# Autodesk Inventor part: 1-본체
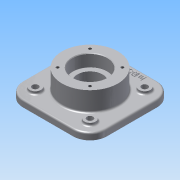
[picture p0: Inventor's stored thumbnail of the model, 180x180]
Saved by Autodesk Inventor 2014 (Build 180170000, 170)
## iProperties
Created: 2015-09
Part Number: 1-본체
Material: 알루미늄 6061
Document SubType Name: Modeling
Designer: study
Density: 2.71 g/cm^3
Appearance: 알루미늄 - 평지
Mass: 1464.68 g
Surface Area: 800.934 cm^2
Volume: 540.471 cm^3
Author: study
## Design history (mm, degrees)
sketch "스케치1"
  geometry: L1 (75, -75)-(-75, -75); L2 (-75, -75)-(-75, 75); L3 (-75, 75)-(75, 75); L4 (75, 75)-(75, -75); L5 (75, -75)-(-75, 75); L6 (-75, -75)-(75, 75); 1 further point
  constraints: 12 end point, 2 midpoint, 2 parallel, 1 horizontal, 1 perpendicular
  dimensions: "d0" = 150 distance of L2.end L3.end; "d1" = 150 distance of L3.end L1.start
extrude "돌출1" new body sketch "스케치1" stored distance "d2" = 12; taper "d3" = 0 deg
node "작업 평면1"
sketch "스케치2"
  geometry: C1 r 50 at (0, 0); 1 further point
  constraints: 1 centre point, 1 coincident
  dimensions: "d5" = 100 diameter of C1
extrude "돌출2" join sketch "스케치2" distance "d6" = 70; taper "d7" = 0 deg
hole "구멍1" diameter "d10" = 45; stored, may be unused: countersink angle "d14" = 90 deg, drill point angle "d16" = 118 deg; dims "d11" = 6, "d12" = 62, "d13" = 22, "d15" = 8, "d26" = 10, "d27" = 10
hole "구멍2" diameter "d19" = 62; stored, may be unused: countersink angle "d23" = 90 deg, drill point angle "d25" = 0 deg; dims "d20" = 6, "d21" = 4, "d22" = 2, "d24" = 22, "d62" = 10, "d63" = 10
fillet "모깎기1" dims "d28" = 30
sketch "스케치3"
  geometry: C1 r 50 at (0, 0) reference; C2 r 10 at (-49, 49); C3 r 10 at (49, 49); C4 r 10 at (49, -49); C5 r 10 at (-49, -49)
  constraints: 4 centre point, 3 equal radius, 2 horizontal alignment, 2 vertical alignment
  dimensions: "d29" = 20 diameter of C2; "d30" = 98 distance of C3.centre C2.centre; "d31" = 49 horizontal distance of C1.centre C2.centre; "d32" = 98 distance of C5.centre C2.centre; "d33" = 49 horizontal distance of C1.centre C5.centre
extrude "돌출3" join sketch "스케치3" distance "d34" = 5; taper "d35" = 0 deg
sketch "스케치4"
  geometry: C1 r 10 at (0, 0) reference; C2 r 10 at (0, -98) reference; C3 r 10 at (98, -98) reference; C4 r 10 at (98, 0) reference; 5 further points
  constraints: 4 coincident
hole "구멍3" sketch "스케치4" at (0, 0), (98, 0), (98, -98), (0, -98) diameter "d36" = 11; stored, may be unused: countersink angle "d40" = 90 deg, drill point angle "d42" = 118 deg; dims "d37" = 6, "d38" = 4, "d39" = 2, "d41" = 22
sketch "스케치5"
  geometry: L1 (28.991, -28.991)-(-28.991, -28.991); L2 (-28.991, -28.991)-(-28.991, 28.991); L3 (-28.991, 28.991)-(28.991, 28.991); L4 (28.991, 28.991)-(28.991, -28.991); L5 (28.991, -28.991)-(-28.991, 28.991); L6 (-28.991, -28.991)-(28.991, 28.991); C1 r 31 at (0, 0) reference; C2 r 50 at (0, 0) reference; 4 further points
  constraints: 12 end point, 4 coincident, 2 midpoint, 2 parallel, 2 perpendicular, 1 horizontal
  dimensions: "d46" = 41 distance of C1.centre L2.end
hole "구멍4" sketch "스케치5" at (-28.991, 28.991), (-28.991, -28.991), (28.991, -28.991), (28.991, 28.991) diameter "d47" = 4.917; stored, may be unused: countersink angle "d51" = 90 deg, drill point angle "d53" = 118 deg; dims "d48" = 10, "d49" = 4, "d50" = 2, "d52" = 13
node "작업 평면2"
sketch "스케치6"
  geometry: C1 r 50 at (0, 0) reference; 1 further point
  constraints: 1 vertical alignment, 1 other
  dimensions: "d54" = 65 distance of C1.centre point (0, 65)
feature "엠보싱1" sketch "스케치6" dims "d0" = 150, "d1" = 150, "d55" = 1, "d56" = 0
fillet "모깎기2" dims "d57" = 3, "d58" = 0.3
chamfer "모따기1" distance "d59" = 1; stored, may be unused: second distance "d60" = 2, angle "d61" = 45 deg
node "솔리드1"
mirror "대칭1"
node "투영된 루프1"
node "투영된 루프2"
node "투영된 루프3"
other parameters: "d4" = 23
